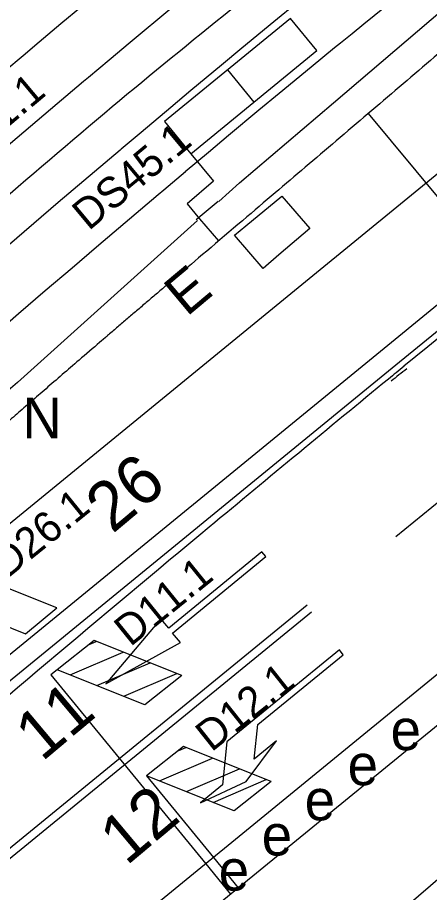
# Model space of a CAD drawing. Extents: x 81617 to 82144, y 454649 to 455150.
# Drawn here: x 81867.65 to 81877.73, y 454904.5 to 454925.92 of the extents above; entities that cross this region are included whole.
import ezdxf

# ---------------------------------------------------------------- set-up
doc = ezdxf.new("R2010")
doc.units = 0
for name, color, linetype in [('B-WE-OG-TOPOGRAFIE-G', 7, 'Continuous'), ('B-WE-VW-MARKERING-G', 7, 'Continuous'), ('N-OI-KL-VRI_KABEL_DETECTIE-G', 7, 'Continuous'), ('N-OI-KL-VRI_KABEL_DETECTIE_SELECTIEF-G', 7, 'Continuous'), ('N-OI-KL-VRI_KABELGEUL-G', 7, 'Continuous'), ('N-OI-KL-VRI_LUS_DETECTIE-G', 7, 'Continuous'), ('N-OI-KL-VRI_LUS_DETECTIE-T18', 7, 'Continuous'), ('N-OI-KL-VRI_LUS_DETECTIE_SELECTIEF-G', 7, 'Continuous'), ('N-OI-KL-VRI_LUS_DETECTIE_SELECTIEF-T18', 7, 'Continuous'), ('N-WE-VW-VRI_RICHTINGNUMMER-T25', 7, 'Continuous')]:
    doc.layers.add(name, color=color, linetype=linetype)

msp = doc.modelspace()

# ---------------------------------------------------------------- linework, layer by layer
at = {"layer": 'B-WE-OG-TOPOGRAFIE-G'}
for p, q in [((81884.055, 454927.107), (81874.789, 454919.522)), ((81885.941, 454924.802), (81876.995, 454917.479)), ((81873.083, 454921.869), (81872.575, 454921.413)), ((81872.056, 454920.946), (81867.654, 454916.986)), ((81874.789, 454919.522), (81858.749, 454906.393)), ((81876.617, 454917.816), (81865.095, 454908.385)), ((81876.995, 454917.479), (81865.412, 454907.998)), ((81881.705, 454912.935), (81868.159, 454901.847)), ((81884.598, 454910.533), (81865.6, 454894.244))]:
    msp.add_line(p, q, dxfattribs=at)
for points in [[(82052.863, 455062.717), (81907.219, 454951.42), (81881.918, 454932.086), (81881.368, 454931.665), (81879.897, 454930.54), (81879.014, 454929.861), (81878.133, 454929.178), (81876.818, 454928.147), (81876.529, 454927.916), (81876.383, 454927.802), (81875.945, 454927.452), (81875.222, 454926.872), (81874.931, 454926.636), (81874.646, 454926.404), (81874.501, 454926.287), (81873.923, 454925.815), (81873.138, 454925.168), (81872.64, 454924.754), (81871.896, 454924.132), (81871.4, 454923.716), (81870.675, 454923.104)], [(82053.734, 455061.577), (81908.09, 454950.28), (81882.79, 454930.946), (81882.24, 454930.525), (81880.77, 454929.401), (81879.891, 454928.725), (81879.015, 454928.046), (81877.708, 454927.021), (81877.419, 454926.791), (81877.274, 454926.677), (81876.842, 454926.332), (81876.122, 454925.754), (81875.835, 454925.522), (81875.549, 454925.289), (81875.405, 454925.173), (81874.834, 454924.706), (81874.053, 454924.062), (81873.558, 454923.651), (81872.817, 454923.032), (81872.324, 454922.618), (81871.758, 454922.14)], [(81873.083, 454921.869), (81875.385, 454923.83), (81882.216, 454929.671), (81883.773, 454930.953), (81919.061, 454957.857), (81919.157, 454957.774)], [(81868.186, 454925.321), (81868.716, 454925.768), (81869.227, 454926.198), (81869.739, 454926.627), (81870.509, 454927.269), (81871.54, 454928.121), (81871.838, 454928.365), (81871.987, 454928.488), (81872.286, 454928.732), (81872.586, 454928.975), (81872.735, 454929.097), (81873.185, 454929.46), (81873.787, 454929.944), (81873.938, 454930.064), (81874.088, 454930.185), (81874.692, 454930.665), (81874.995, 454930.904), (81875.146, 454931.024), (81875.45, 454931.262), (81875.755, 454931.502), (81876.367, 454931.98), (81877.287, 454932.693), (81878.516, 454933.638)], [(81869.269, 454924.357), (81869.386, 454924.456), (81869.641, 454924.67), (81869.895, 454924.885), (81870.405, 454925.313), (81871.426, 454926.165), (81872.194, 454926.801), (81873.044, 454927.498), (81873.49, 454927.861)], [(81867.793, 454924.989), (81868.187, 454925.321)], [(81868.186, 454925.321), (81868.187, 454925.321)], [(81885.624, 454925.189), (81876.617, 454917.816)], [(81867.442, 454924.691), (81867.696, 454924.907), (81867.793, 454924.989)], [(81868.836, 454923.991), (81869.27, 454924.358)], [(81869.269, 454924.357), (81869.27, 454924.358)], [(81867.318, 454922.705), (81868.623, 454923.811), (81868.836, 454923.991)], [(81870.676, 454923.105), (81870.19, 454922.694)], [(81870.676, 454923.105), (81870.676, 454923.104)], [(81870.19, 454922.694), (81870.166, 454922.674), (81868.649, 454921.388), (81868.055, 454920.874), (81867.4, 454920.315), (81866.74, 454919.75), (81866.33, 454919.397)], [(81871.759, 454922.141), (81871.232, 454921.696)], [(81871.759, 454922.141), (81871.758, 454922.14)], [(81871.232, 454921.696), (81871.093, 454921.579), (81869.583, 454920.298), (81868.99, 454919.785), (81868.332, 454919.224), (81867.675, 454918.662), (81867.133, 454918.194)], [(81873.24, 454920.821), (81874.118, 454921.549), (81874.799, 454920.751)], [(81872.027, 454920.97), (81872.562, 454921.426)], [(81872.561, 454921.426), (81872.562, 454921.426)], [(81874.044, 454920.107), (81873.658, 454919.777), (81872.963, 454920.591), (81873.241, 454920.822)], [(81873.24, 454920.821), (81873.241, 454920.822)], [(81874.799, 454920.751), (81874.044, 454920.106)], [(81874.044, 454920.107), (81874.044, 454920.106)]]:
    msp.add_lwpolyline(points, dxfattribs=at)
msp.add_arc((81921.928, 454856.654), 81.152, 131.97433, 137.09534, dxfattribs=at)
at = {"layer": 'B-WE-VW-MARKERING-G'}
for p, q in [((81887.349, 454921.754), (81876.908, 454913.208)), ((81874.738, 454911.536), (81866.586, 454904.863)), ((81874.843, 454911.363), (81866.733, 454904.725)), ((81875.525, 454910.436), (81872.777, 454908.189)), ((81875.62, 454910.32), (81875.525, 454910.436)), ((81873.53, 454908.611), (81875.62, 454910.32)), ((81873.445, 454907.767), (81873.53, 454908.611)), ((81873.248, 454907.218), (81873.987, 454908.21)), ((81873.987, 454908.21), (81873.445, 454907.767)), ((81872.777, 454908.189), (81872.671, 454907.134)), ((81872.129, 454906.691), (81873.248, 454907.218)), ((81872.671, 454907.134), (81872.129, 454906.691))]:
    msp.add_line(p, q, dxfattribs=at)
msp.add_lwpolyline([(81869.813, 454909.61), (81871.636, 454910.619), (81871.446, 454910.851), (81873.728, 454912.721), (81873.633, 454912.837), (81871.351, 454910.967), (81871.161, 454911.199)], close=True, dxfattribs=at)
for centre, radius, start, end in [((82446.303, 454224.11), 897, 126.319161, 129.387113), ((81981.123, 454790.703), 173.353, 127.40351, 129.88035), ((82000.87, 454767.62), 203.728, 129.97975, 131.1142), ((82446.303, 454224.11), 897, 129.387074, 129.418475), ((82921.596, 453593.134), 1686.5, 128.263815, 128.280472), ((82446.303, 454224.11), 897, 129.387074, 129.387113), ((82921.596, 453593.134), 1686.5, 128.263815, 128.263836), ((82446.303, 454224.11), 897, 129.418475, 129.782144), ((82446.303, 454224.11), 897, 129.782144, 130.440328)]:
    msp.add_arc(centre, radius, start, end, dxfattribs=at)
at = {"layer": 'N-OI-KL-VRI_KABEL_DETECTIE-G'}
for p, q in [((81876.232, 454923.568), (81877.957, 454921.492)), ((81870.809, 454907.356), (81872.446, 454905.356))]:
    msp.add_line(p, q, dxfattribs=at)
msp.add_lwpolyline([(81868.62, 454909.952), (81868.472, 454909.83), (81872.26, 454905.203)], dxfattribs=at)
at = {"layer": 'N-OI-KL-VRI_KABEL_DETECTIE_SELECTIEF-G'}
msp.add_lwpolyline([(81871.896, 454922.585), (81872.445, 454921.915), (81871.804, 454921.357), (81872.108, 454920.992)], dxfattribs=at)
at = {"layer": 'N-OI-KL-VRI_KABELGEUL-G'}
for p, q in [((81872.26, 454905.203), (81872.866, 454904.461)), ((81872.446, 454905.356), (81873.053, 454904.614))]:
    msp.add_line(p, q, dxfattribs=at)
for points in [[(81872.108, 454920.992), (81872.571, 454920.448)], [(81868.039, 454900.514), (81884.291, 454913.804)]]:
    msp.add_lwpolyline(points, dxfattribs=at)
msp.add_open_spline([(81966.954, 454994.044), (81954.516, 454984.42), (81942.079, 454974.796), (81941.008, 454974.125), (81939.937, 454973.455), (81933.631, 454968.575), (81927.325, 454963.696), (81926.798, 454963.288), (81926.621, 454962.646), (81926.355, 454961.682), (81926.09, 454960.718), (81925.901, 454960.035), (81925.325, 454959.623), (81922.434, 454957.557), (81919.543, 454955.49), (81917.87, 454954.23), (81916.197, 454952.97), (81913.406, 454950.849), (81910.615, 454948.728), (81908.564, 454947.145), (81906.513, 454945.562), (81905.944, 454945.123), (81905.225, 454945.147), (81904.815, 454945.16), (81904.405, 454945.174), (81903.693, 454945.197), (81903.126, 454944.765), (81893.683, 454937.565), (81884.239, 454930.365), (81883.469, 454929.731), (81882.698, 454929.096), (81879.285, 454926.178), (81875.872, 454923.259), (81872.421, 454920.321), (81868.97, 454917.382), (81867.082, 454915.724), (81865.195, 454914.067), (81863.45, 454912.271), (81861.704, 454910.475), (81860.838, 454909.482), (81859.972, 454908.49), (81859.86, 454908.361), (81859.97, 454908.23), (81860.094, 454908.077), (81860.218, 454907.925), (81863.368, 454903.762), (81866.518, 454899.599), (81866.598, 454899.497), (81866.679, 454899.395)], degree=4, dxfattribs=at)
at = {"layer": 'N-OI-KL-VRI_LUS_DETECTIE-G'}
for p, q in [((81868.618, 454911.469), (81866.684, 454912.24)), ((81865.911, 454911.605), (81867.845, 454910.834)), ((81867.845, 454910.834), (81868.618, 454911.469)), ((81869.528, 454910.667), (81868.62, 454909.952)), ((81869.41, 454910.574), (81869.578, 454910.647)), ((81871.67, 454909.812), (81869.528, 454910.667)), ((81868.938, 454909.826), (81870.234, 454910.385)), ((81869.595, 454909.565), (81870.895, 454910.122)), ((81870.766, 454909.096), (81868.62, 454909.952)), ((81870.253, 454909.302), (81871.548, 454909.861)), ((81871.67, 454909.812), (81870.766, 454909.096)), ((81871.717, 454908.071), (81870.809, 454907.356)), ((81871.6, 454907.978), (81871.768, 454908.051)), ((81873.86, 454907.216), (81871.717, 454908.071)), ((81871.128, 454907.23), (81872.424, 454907.789)), ((81872.955, 454906.5), (81870.809, 454907.356)), ((81871.785, 454906.969), (81873.084, 454907.526)), ((81872.442, 454906.705), (81873.737, 454907.265)), ((81873.86, 454907.216), (81872.955, 454906.5))]:
    msp.add_line(p, q, dxfattribs=at)
at = {"layer": 'N-OI-KL-VRI_LUS_DETECTIE_SELECTIEF-G'}
for p, q in [((81874.334, 454925.898), (81871.252, 454923.371)), ((81874.978, 454925.112), (81874.334, 454925.898)), ((81871.896, 454922.585), (81874.978, 454925.112)), ((81872.793, 454924.635), (81873.437, 454923.849)), ((81871.252, 454923.371), (81871.896, 454922.585))]:
    msp.add_line(p, q, dxfattribs=at)

# ---------------------------------------------------------------- texts
at = {"layer": 'B-WE-OG-TOPOGRAFIE-G'}
msp.add_text('E', height=1, rotation=39.9844, dxfattribs=at).set_placement((81871.791, 454918.578))
for s, p in [('N', (81867.772, 454915.616)), ('e', (81876.778, 454907.984)), ('e', (81875.728, 454907.125)), ('e', (81874.677, 454906.265)), ('e', (81873.626, 454905.405)), ('e', (81872.575, 454904.545))]:
    msp.add_text(s, height=1, dxfattribs=at).set_placement(p)
at = {"layer": 'N-OI-KL-VRI_LUS_DETECTIE-T18'}
for s, rotation, p in [('D51.1', 39.974, (81866.335, 454922.317)), ('D26.1', 38.9894, (81867.4, 454912.17)), ('D11.1', 38.9894, (81870.411, 454910.499)), ('D12.1', 38.4616, (81872.395, 454907.922))]:
    msp.add_text(s, height=0.75, rotation=rotation, dxfattribs=at).set_placement(p)
at = {"layer": 'N-OI-KL-VRI_LUS_DETECTIE_SELECTIEF-T18'}
msp.add_text('DS45.1', height=0.75, rotation=39.7963, dxfattribs=at).set_placement((81869.393, 454920.682))
at = {"layer": 'N-WE-VW-VRI_RICHTINGNUMMER-T25'}
for s, p in [('26', (81869.975, 454913.266)), ('11', (81868.25, 454907.684)), ('12', (81870.317, 454905.138))]:
    msp.add_text(s, height=1.2, rotation=40, dxfattribs=at).set_placement(p)

doc.saveas('drawing.dxf')
